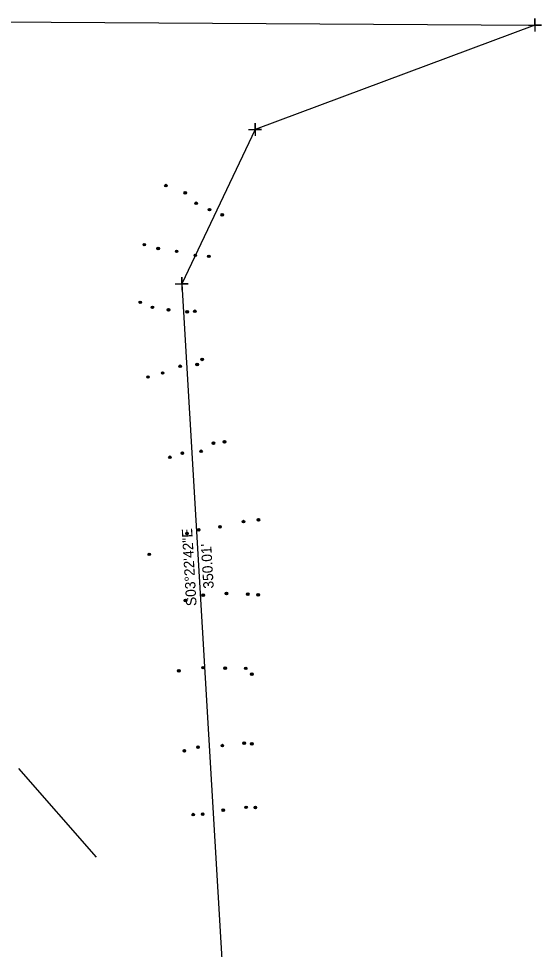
# Model space of a CAD drawing. Extents: x 1550153 to 1552579, y 809637 to 812160.
# Drawn here: x 1552376.2 to 1552579, y 809876 to 810237.2 of the extents above; entities that cross this region are included whole.
import ezdxf

# ---------------------------------------------------------------- set-up
doc = ezdxf.new("R2010")
doc.units = 0
for name, color, linetype in [('Default', 7, 'Continuous'), ('Exist Property Corner CELL', 7, 'Continuous'), ('Exist Property Line', 7, 'Continuous'), ('Exist Property Line Text', 7, 'Continuous'), ('Exist Right of Way Line', 7, 'Continuous')]:
    doc.layers.add(name, color=color, linetype=linetype)

# ---------------------------------------------------------------- blocks, each defined once
blk = doc.blocks.new('SurveyPointCell')
at = {"layer": 'Default'}
for p, q in [((-0.5, 0), (0.5, 0)), ((0, -0.5), (0, 0.5))]:
    blk.add_line(p, q, dxfattribs=at)
blk.add_circle((0, 0), 0.5, dxfattribs=at)

msp = doc.modelspace()

# ---------------------------------------------------------------- linework, layer by layer
at = {"layer": 'Exist Property Corner CELL'}
for p, q in [((1552576.51, 810234.75), (1552576.51, 810234.75)), ((1552467.97, 810194.22), (1552467.97, 810194.22)), ((1552439.52, 810134.36), (1552439.52, 810134.36))]:
    msp.add_line(p, q, dxfattribs=at)
for points in [[(1552574.01, 810234.75), (1552579.01, 810234.75), (1552576.51, 810234.75), (1552576.51, 810237.25), (1552576.51, 810232.25)], [(1552465.47, 810194.22), (1552470.47, 810194.22), (1552467.97, 810194.22), (1552467.97, 810196.72), (1552467.97, 810191.72)], [(1552437.02, 810134.36), (1552442.02, 810134.36), (1552439.52, 810134.36), (1552439.52, 810136.86), (1552439.52, 810131.86)]]:
    msp.add_lwpolyline(points, dxfattribs=at)
at = {"layer": 'Exist Property Line'}
for p, q in [((1552150.95, 810237.19), (1552576.51, 810234.75)), ((1552576.51, 810234.75), (1552467.97, 810194.22)), ((1552467.97, 810194.22), (1552439.52, 810134.36)), ((1552439.52, 810134.36), (1552460.15, 809784.96))]:
    msp.add_line(p, q, dxfattribs=at)
at = {"layer": 'Exist Right of Way Line'}
msp.add_line((1552376.25, 809946.17), (1552406.32, 809911.81), dxfattribs=at)

# ---------------------------------------------------------------- block references
at = {"layer": 'Default'}
for p in [(1552433.38, 810172.44), (1552433.38, 810172.44), (1552440.89, 810169.62), (1552440.89, 810169.62), (1552445.1, 810165.59), (1552445.1, 810165.59), (1552450.26, 810163.08), (1552450.26, 810163.08), (1552455.23, 810161.07), (1552455.23, 810161.07), (1552424.99, 810149.52), (1552424.99, 810149.52), (1552430.37, 810148.02), (1552430.37, 810148.02), (1552437.54, 810146.92), (1552437.54, 810146.92), (1552444.78, 810145.37), (1552444.78, 810145.37), (1552450.04, 810144.99), (1552450.04, 810144.99), (1552423.43, 810127.12), (1552423.43, 810127.12), (1552428.13, 810125.19), (1552428.13, 810125.19), (1552434.35, 810124.23), (1552434.35, 810124.23), (1552441.59, 810123.43), (1552441.59, 810123.43), (1552444.6, 810123.66), (1552444.6, 810123.66), (1552438.9, 810102.32), (1552438.9, 810102.32), (1552445.47, 810102.98), (1552445.47, 810102.98), (1552447.46, 810104.99), (1552447.46, 810104.99), (1552432.1, 810099.7), (1552432.1, 810099.7), (1552426.43, 810098.16), (1552426.43, 810098.16), (1552451.8, 810072.44), (1552451.8, 810072.44), (1552456.12, 810072.98), (1552456.12, 810072.98), (1552434.94, 810066.99), (1552434.94, 810066.99), (1552439.76, 810068.59), (1552439.76, 810068.59), (1552447.02, 810069.33), (1552447.02, 810069.33), (1552463.49, 810042.02), (1552463.49, 810042.02), (1552469.25, 810042.73), (1552469.25, 810042.73), (1552441.57, 810037.38), (1552441.57, 810037.38), (1552446.09, 810038.83), (1552446.09, 810038.83), (1552454.36, 810039.99), (1552454.36, 810039.99), (1552426.92, 810029.34), (1552426.92, 810029.34), (1552447.82, 810013.47), (1552447.82, 810013.47), (1552456.83, 810014.14), (1552456.83, 810014.14), (1552465.12, 810013.87), (1552465.12, 810013.87), (1552469.18, 810013.62), (1552469.18, 810013.62), (1552440.96, 810011.43), (1552440.96, 810011.43), (1552438.38, 809984.09), (1552438.38, 809984.09), (1552447.83, 809985.32), (1552447.83, 809985.32), (1552456.39, 809985.17), (1552456.39, 809985.17), (1552464.34, 809985.09), (1552464.34, 809985.09), (1552466.7, 809982.81), (1552466.7, 809982.81), (1552445.82, 809954.48), (1552445.82, 809954.48), (1552455.27, 809955.08), (1552455.27, 809955.08), (1552463.74, 809956.04), (1552463.74, 809956.04), (1552466.7, 809955.75), (1552466.7, 809955.75), (1552440.53, 809953.06), (1552440.53, 809953.06), (1552455.62, 809930.01), (1552455.62, 809930.01), (1552464.46, 809931.12), (1552464.46, 809931.12), (1552468.07, 809931.07), (1552468.07, 809931.07), (1552443.98, 809928.31), (1552443.98, 809928.31), (1552447.64, 809928.49), (1552447.64, 809928.49)]:
    msp.add_blockref('SurveyPointCell', p, dxfattribs=at)

# ---------------------------------------------------------------- texts
at = {"layer": 'Exist Property Line Text'}
for s, p in [('S03°22\'42"E', (1552445.3, 810009.34)), ("350.01'", (1552451.95, 810016.12))]:
    msp.add_text(s, height=4.02, rotation=93.3783, dxfattribs=at).set_placement(p)

doc.saveas('drawing.dxf')
